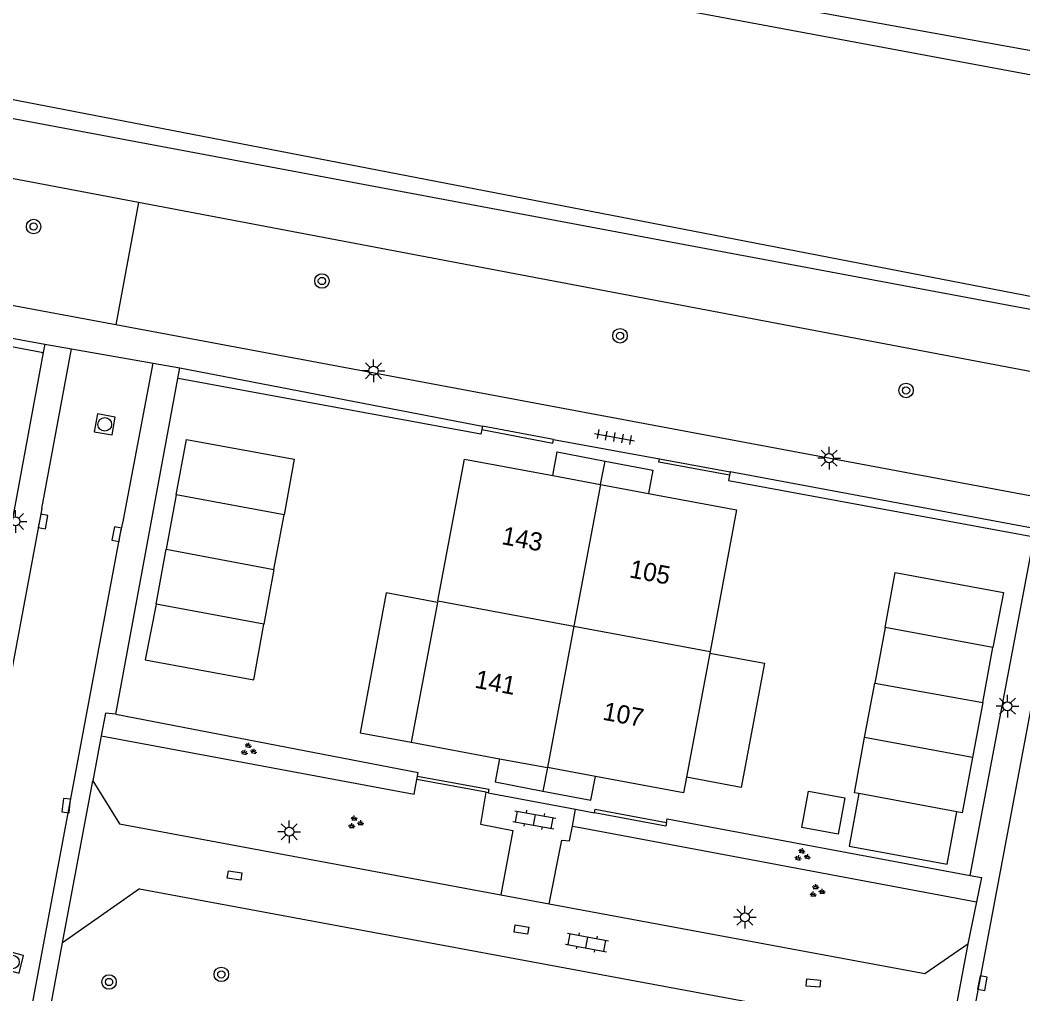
# Model space of a CAD drawing. Extents: x 124000 to 128010, y 398999 to 403000.
# Drawn here: x 126780.7 to 126835.9, y 399506.5 to 399560.1 of the extents above; entities that cross this region are included whole.
import ezdxf

# ---------------------------------------------------------------- set-up
doc = ezdxf.new("R2010")
doc.units = 0
for name, color, linetype in [('gg-afsc-hekwerk', 7, 'Continuous'), ('gg-afsc-muur', 7, 'Continuous'), ('gg-anno-huisnummerreeks BGT', 7, 'Continuous'), ('gg-bbg-bijgebouw', 7, 'Continuous'), ('gg-bbg-gedigitaliseerde bijgebouw', 7, 'Continuous'), ('gg-bbg-hoofdgebouw', 7, 'Continuous'), ('gg-bbg-luifel en loopbrug', 7, 'Continuous'), ('gg-bbg-tussenscheiding', 7, 'Continuous'), ('gg-knt-BGT kruinlijn', 7, 'Continuous'), ('gg-knt-verharding', 7, 'Continuous'), ('gg-kntw-beschoeiing', 7, 'Continuous'), ('gt-grn-groengrens', 7, 'Continuous'), ('gt-grn-vlakafsluiter', 7, 'Continuous'), ('gt-grn-weggrens', 7, 'Continuous'), ('gt-symb-boom', 7, 'Continuous'), ('gt-symb-groenvak', 7, 'Continuous'), ('gt-symb-klinker verharding', 7, 'Continuous'), ('gt-symb-kolk', 7, 'Continuous'), ('gt-symb-kolk center center', 7, 'Continuous'), ('gt-symb-lichtmast', 7, 'Continuous'), ('gt-symb-rioolschacht', 7, 'Continuous'), ('gt-symb-tegel verharding', 7, 'Continuous')]:
    doc.layers.add(name, color=color, linetype=linetype)

# ---------------------------------------------------------------- blocks, each defined once
blk = doc.blocks.new('gt0-KOLK')
at = {"layer": 'gt-symb-kolk'}
blk.add_lwpolyline([(0, 0), (0.375, 0), (0.375, 0.4), (-0.375, 0.4), (-0.375, 0), (0, 0)], dxfattribs=at)
blk = doc.blocks.new('gt0-LMAST')
at = {"layer": 'gt-symb-lichtmast'}
for p, q in [((-0.005, 0.246), (-0.005, 0.621)), ((-0.182, 0.173), (-0.447, 0.438)), ((0.172, 0.173), (0.437, 0.438)), ((-0.255, -0.004), (-0.63, -0.004)), ((-0.182, -0.181), (-0.447, -0.446)), ((-0.005, -0.254), (-0.005, -0.629)), ((0.437, -0.446), (0.172, -0.181)), ((0.245, -0.004), (0.62, -0.004))]:
    blk.add_line(p, q, dxfattribs=at)
blk.add_circle((-0.005, -0.004), 0.25, dxfattribs=at)
blk = doc.blocks.new('gt0-BOOM')
at = {"layer": 'gt-symb-boom'}
for radius in [0.4, 0.2]:
    blk.add_circle((0, 0), radius, dxfattribs=at)
blk = doc.blocks.new('gt0-GRVAK')
at = {"layer": 'gt-symb-groenvak'}
for p, q in [((-0.11, 0.189), (-0.228, 0.24)), ((-0.182, 0.153), (0.088, 0.153)), ((-0.091, 0.211), (-0.156, 0.322)), ((-0.047, 0.214), (-0.047, 0.393)), ((-0.004, 0.211), (0.061, 0.322)), ((0.015, 0.189), (0.133, 0.24)), ((0.262, -0.052), (0.197, 0.059)), ((0.305, -0.049), (0.305, 0.13)), ((0.349, -0.052), (0.414, 0.059)), ((-0.245, -0.228), (-0.363, -0.177)), ((-0.318, -0.264), (-0.047, -0.264)), ((-0.226, -0.206), (-0.291, -0.095)), ((-0.183, -0.203), (-0.183, -0.024)), ((-0.139, -0.206), (-0.074, -0.095)), ((-0.12, -0.228), (-0.002, -0.177)), ((0.243, -0.074), (0.125, -0.023)), ((0.17, -0.11), (0.441, -0.11)), ((0.368, -0.074), (0.486, -0.023))]:
    blk.add_line(p, q, dxfattribs=at)
blk = doc.blocks.new('gt0-TEG1')
at = {"layer": 'gt-symb-tegel verharding'}
for p, q in [((-1.125, 0), (1.125, 0)), ((-0.9, -0.25), (-0.9, 0.25)), ((-0.45, -0.25), (-0.45, 0.25)), ((0, -0.25), (0, 0.25)), ((0.45, -0.25), (0.45, 0.25)), ((0.9, -0.25), (0.9, 0.25))]:
    blk.add_line(p, q, dxfattribs=at)
blk = doc.blocks.new('gt0-KL1')
at = {"layer": 'gt-symb-klinker verharding'}
for p, q in [((-1.15, 0.3), (1.15, 0.3)), ((-1, -0.3), (-1, 0.3)), ((-0.5, 0.3), (-0.5, 0.45)), ((0, -0.3), (0, 0.3)), ((0.5, 0.3), (0.5, 0.45)), ((1, -0.3), (1, 0.3)), ((-1.15, -0.3), (1.15, -0.3)), ((-0.5, -0.45), (-0.5, -0.3)), ((0.5, -0.45), (0.5, -0.3))]:
    blk.add_line(p, q, dxfattribs=at)
blk = doc.blocks.new('gt0-KOLKCC')
at = {"layer": 'gt-symb-kolk center center'}
blk.add_lwpolyline([(-0.375, 0.2), (0.375, 0.2), (0.375, -0.2), (-0.375, -0.2)], close=True, dxfattribs=at)
blk = doc.blocks.new('gt0-RS')
at = {"layer": 'gt-symb-rioolschacht'}
blk.add_lwpolyline([(-0.5, -0.5), (0.5, -0.5), (0.5, 0.5), (-0.5, 0.5)], close=True, dxfattribs=at)
blk.add_circle((0, 0), 0.375, dxfattribs=at)

msp = doc.modelspace()

# ---------------------------------------------------------------- linework, layer by layer
at = {"layer": 'gg-afsc-hekwerk'}
for p, q in [((126781.846, 399541.841), (126765.496, 399544.831)), ((126806.048, 399537.335), (126789.372, 399540.394)), ((126819.677, 399534.791), (126836.523, 399531.69)), ((126785.931, 399521.922), (126802.585, 399518.705)), ((126816.307, 399516.161), (126832.985, 399513.037))]:
    msp.add_line(p, q, dxfattribs=at)
at = {"layer": 'gg-afsc-muur'}
for p, q in [((126806.13, 399537.772), (126806.095, 399537.589)), ((126810.049, 399537.042), (126806.13, 399537.772)), ((126815.875, 399535.976), (126819.765, 399535.264)), ((126819.765, 399535.264), (126819.731, 399535.078)), ((126802.515, 399518.325), (126802.55, 399518.516)), ((126806.323, 399517.621), (126802.515, 399518.325)), ((126806.439, 399517.6), (126806.323, 399517.621))]:
    msp.add_line(p, q, dxfattribs=at)
for points in [[(126806.095, 399537.589), (126810.01, 399536.838), (126810.049, 399537.042)], [(126819.731, 399535.078), (126815.84, 399535.788), (126815.875, 399535.976)], [(126802.55, 399518.516), (126806.474, 399517.791), (126806.439, 399517.6)], [(126812.307, 399516.486), (126812.344, 399516.687), (126816.269, 399515.959)], [(126816.269, 399515.959), (126816.232, 399515.758), (126812.307, 399516.486)]]:
    msp.add_lwpolyline(points, dxfattribs=at)
at = {"layer": 'gg-bbg-bijgebouw'}
for p, q in [((126789.264, 399533.997), (126788.714, 399531.004)), ((126795.202, 399532.905), (126789.264, 399533.997)), ((126794.648, 399529.896), (126795.202, 399532.905)), ((126788.157, 399527.975), (126788.714, 399531.004)), ((126794.648, 399529.896), (126794.094, 399526.883)), ((126794.094, 399526.883), (126788.157, 399527.975)), ((126828.302, 399526.696), (126827.734, 399523.638)), ((126834.244, 399525.592), (126828.302, 399526.696)), ((126833.681, 399522.562), (126834.244, 399525.592)), ((126827.179, 399520.647), (126827.734, 399523.638)), ((126833.681, 399522.562), (126833.12, 399519.544)), ((126833.12, 399519.544), (126827.179, 399520.647))]:
    msp.add_line(p, q, dxfattribs=at)
at = {"layer": 'gg-bbg-gedigitaliseerde bijgebouw'}
msp.add_lwpolyline([(126824.092, 399517.682), (126826.087, 399517.314), (126825.718, 399515.32), (126823.724, 399515.688), (126824.092, 399517.682)], dxfattribs=at)
at = {"layer": 'gg-bbg-hoofdgebouw'}
for p, q in [((126809.996, 399535.062), (126812.635, 399534.57)), ((126812.635, 399534.57), (126815.274, 399534.078)), ((126803.653, 399528.067), (126802.211, 399520.374)), ((126803.672, 399528.168), (126803.653, 399528.067)), ((126818.649, 399525.284), (126817.37, 399518.447)), ((126818.665, 399525.371), (126818.649, 399525.284)), ((126802.211, 399520.374), (126807.068, 399519.471)), ((126807.068, 399519.471), (126809.707, 399518.98)), ((126812.346, 399518.489), (126809.707, 399518.98))]:
    msp.add_line(p, q, dxfattribs=at)
for points in [[(126803.672, 399528.168), (126805.134, 399535.968), (126809.996, 399535.062)], [(126815.274, 399534.078), (126820.125, 399533.175), (126818.665, 399525.371)], [(126817.37, 399518.447), (126817.209, 399517.584), (126812.346, 399518.489)]]:
    msp.add_lwpolyline(points, dxfattribs=at)
at = {"layer": 'gg-bbg-luifel en loopbrug'}
for p, q in [((126812.635, 399534.57), (126812.881, 399535.859)), ((126809.707, 399518.98), (126809.461, 399517.691)), ((126832.247, 399516.549), (126826.859, 399517.549))]:
    msp.add_line(p, q, dxfattribs=at)
for points in [[(126789.264, 399533.997), (126789.829, 399537.045), (126795.763, 399535.953), (126795.202, 399532.905)], [(126809.996, 399535.062), (126810.245, 399536.363), (126812.881, 399535.859)], [(126812.881, 399535.859), (126815.518, 399535.354), (126815.274, 399534.078)], [(126828.302, 399526.696), (126828.865, 399529.727), (126834.818, 399528.621), (126834.244, 399525.592)], [(126803.653, 399528.067), (126800.831, 399528.595), (126799.4, 399520.897), (126802.211, 399520.374)], [(126788.157, 399527.975), (126787.551, 399524.913), (126793.53, 399523.814), (126794.094, 399526.883)], [(126818.649, 399525.284), (126821.654, 399524.722), (126820.374, 399517.886), (126817.37, 399518.447)], [(126826.859, 399517.549), (126826.613, 399517.595), (126827.179, 399520.647)], [(126807.068, 399519.471), (126806.824, 399518.196), (126809.461, 399517.691)], [(126833.12, 399519.544), (126832.542, 399516.494), (126832.247, 399516.549)], [(126809.461, 399517.691), (126812.097, 399517.187), (126812.346, 399518.489)], [(126826.859, 399517.549), (126826.326, 399514.664), (126831.714, 399513.668), (126832.247, 399516.549)]]:
    msp.add_lwpolyline(points, dxfattribs=at)
at = {"layer": 'gg-bbg-tussenscheiding'}
for p, q in [((126812.635, 399534.57), (126811.17, 399526.769)), ((126788.714, 399531.004), (126794.648, 399529.896)), ((126803.672, 399528.168), (126811.17, 399526.769)), ((126811.17, 399526.769), (126809.707, 399518.98)), ((126811.17, 399526.769), (126818.665, 399525.371)), ((126827.734, 399523.638), (126833.681, 399522.562))]:
    msp.add_line(p, q, dxfattribs=at)
at = {"layer": 'gg-knt-BGT kruinlijn'}
msp.add_line((126950.486, 399519.162), (126787.178, 399550.094), dxfattribs=at)
msp.add_lwpolyline([(126787.178, 399550.094), (126703.342, 399565.974), (126686.788, 399569.405), (126682.263, 399572.046), (126679.171, 399572.084)], dxfattribs=at)
at = {"layer": 'gg-knt-verharding'}
for p, q in [((126785.932, 399543.354), (126678.7, 399563.39)), ((126765.592, 399545.34), (126782.023, 399542.289)), ((126949.326, 399512.823), (126785.932, 399543.354)), ((126782.023, 399542.289), (126781.937, 399541.824)), ((126782.023, 399542.289), (126783.493, 399542.032)), ((126781.937, 399541.824), (126778.504, 399523.3)), ((126781.855, 399533.25), (126783.493, 399542.032)), ((126783.493, 399542.032), (126787.991, 399541.246)), ((126786.367, 399532.624), (126787.991, 399541.246)), ((126787.991, 399541.246), (126789.453, 399540.991)), ((126789.344, 399540.399), (126789.453, 399540.991)), ((126789.453, 399540.991), (126806.13, 399537.772)), ((126785.931, 399521.922), (126789.344, 399540.399)), ((126810.049, 399537.042), (126815.875, 399535.976)), ((126836.606, 399532.128), (126819.765, 399535.264)), ((126781.855, 399533.25), (126775.653, 399500)), ((126832.985, 399513.037), (126836.523, 399531.69)), ((126836.357, 399522.348), (126832.134, 399500)), ((126785.138, 399520.734), (126784.673, 399518.254)), ((126806.439, 399517.6), (126811.258, 399516.685)), ((126811.084, 399515.764), (126811.258, 399516.685)), ((126787.248, 399512.313), (126783.004, 399509.344)), ((126787.248, 399512.313), (126828.442, 399504.675)), ((126807.149, 399511.981), (126809.811, 399511.486)), ((126833.338, 399511.601), (126832.854, 399509.272)), ((126782.371, 399505.967), (126783.004, 399509.344))]:
    msp.add_line(p, q, dxfattribs=at)
for points in [[(126780.221, 399500), (126786.183, 399531.789), (126786.367, 399532.624)], [(126785.931, 399521.922), (126785.371, 399521.98), (126785.138, 399520.734)], [(126784.673, 399518.254), (126786.133, 399515.887), (126807.149, 399511.981)], [(126806.323, 399517.621), (126806.012, 399515.874), (126807.796, 399515.513), (126807.149, 399511.981)], [(126809.811, 399511.486), (126810.494, 399514.995), (126810.931, 399514.957), (126811.084, 399515.764)], [(126832.985, 399513.037), (126833.616, 399512.939), (126833.338, 399511.601)], [(126809.811, 399511.486), (126830.484, 399507.644), (126832.854, 399509.272)]]:
    msp.add_lwpolyline(points, dxfattribs=at)
at = {"layer": 'gg-kntw-beschoeiing'}
for p, q in [((126869.97, 399550.825), (126754.532, 399572.364)), ((126814.862, 399549.063), (126758.462, 399559.96)), ((126867.862, 399538.822), (126814.862, 399549.063))]:
    msp.add_line(p, q, dxfattribs=at)
at = {"layer": 'gt-grn-groengrens'}
for p, q in [((126787.178, 399550.094), (126785.932, 399543.354)), ((126811.258, 399516.685), (126812.307, 399516.486)), ((126811.084, 399515.764), (126811.503, 399515.685)), ((126811.503, 399515.685), (126833.338, 399511.601))]:
    msp.add_line(p, q, dxfattribs=at)
for points in [[(127031.407, 399516.954), (127031.756, 399518.92), (127029.879, 399522.161), (127009.635, 399525.925), (127000, 399527.778), (126870.175, 399551.993), (126857.55, 399554.628), (126778.853, 399568.809), (126692.438, 399585.276), (126688.731, 399584.708)], [(126679.888, 399575.899), (126683.061, 399575.383), (126687.279, 399572.619), (126691.934, 399571.31), (126814.728, 399548.258), (126867.774, 399538.33), (127022.231, 399507.612), (127025.36, 399507.675), (127027.276, 399508.355), (127030.476, 399511.716), (127030.741, 399513.207)], [(126785.138, 399520.734), (126802.366, 399517.512), (126802.515, 399518.325)]]:
    msp.add_lwpolyline(points, dxfattribs=at)
at = {"layer": 'gt-grn-vlakafsluiter'}
for p, q in [((126781.846, 399541.841), (126781.937, 399541.824)), ((126789.344, 399540.399), (126789.372, 399540.394)), ((126806.095, 399537.589), (126806.048, 399537.335)), ((126819.731, 399535.078), (126819.677, 399534.791)), ((126802.55, 399518.516), (126802.585, 399518.705)), ((126816.269, 399515.959), (126816.307, 399516.161))]:
    msp.add_line(p, q, dxfattribs=at)
at = {"layer": 'gt-grn-weggrens'}
for p, q in [((126783.004, 399509.344), (126784.673, 399518.254)), ((126832.854, 399509.272), (126831.228, 399500.561))]:
    msp.add_line(p, q, dxfattribs=at)

# ---------------------------------------------------------------- block references
at = {"layer": 'gt-symb-boom'}
for p in [(126781.41, 399548.765), (126797.289, 399545.769), (126813.705, 399542.752), (126829.459, 399539.746), (126791.747, 399507.599), (126785.562, 399507.18)]:
    msp.add_blockref('gt0-BOOM', p, dxfattribs=at)
at = {"layer": 'gt-symb-groenvak'}
for p, rotation in [((126793.236, 399519.954), -10.950434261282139), ((126823.73, 399514.146), -10.602058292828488)]:
    msp.add_blockref('gt0-GRVAK', p, dxfattribs=dict(at, rotation=rotation))
for p in [(126799.117, 399515.952), (126824.532, 399512.18)]:
    msp.add_blockref('gt0-GRVAK', p, dxfattribs=at)
at = {"layer": 'gt-symb-klinker verharding'}
for p, rotation in [((126808.99, 399516.105), -10.30997039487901), ((126811.883, 399509.354), -10.545734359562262)]:
    msp.add_blockref('gt0-KL1', p, dxfattribs=dict(at, rotation=rotation))
at = {"layer": 'gt-symb-kolk'}
for p, rotation in [((126781.73, 399532.564), -100.30997039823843), ((126786.183, 399531.789), 79.39794170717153), ((126783.403, 399516.863), 83.22321716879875), ((126833.467, 399507.148), -100.78161673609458)]:
    msp.add_blockref('gt0-KOLK', p, dxfattribs=dict(at, rotation=rotation))
at = {"layer": 'gt-symb-kolk center center'}
for p, rotation in [((126792.476, 399513.043), 171.72410716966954), ((126808.276, 399510.065), -8.802804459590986), ((126824.347, 399507.119), 174.83669318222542)]:
    msp.add_blockref('gt0-KOLKCC', p, dxfattribs=dict(at, rotation=rotation))
at = {"layer": 'gt-symb-lichtmast'}
for p in [(126800.133, 399540.831), (126825.222, 399536.02), (126780.415, 399532.536), (126835.046, 399522.365), (126795.491, 399515.454), (126820.592, 399510.747)]:
    msp.add_blockref('gt0-LMAST', p, dxfattribs=at)
at = {"layer": 'gt-symb-rioolschacht'}
for p, rotation in [((126785.328, 399537.877), 79.74640197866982), ((126780.244, 399508.28), 75.93596328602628)]:
    msp.add_blockref('gt0-RS', p, dxfattribs=dict(at, rotation=rotation))
at = {"layer": 'gt-symb-tegel verharding', "rotation": -10.366322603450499}
msp.add_blockref('gt0-TEG1', (126813.402, 399537.18), dxfattribs=at)

# ---------------------------------------------------------------- texts
at = {"layer": 'gg-anno-huisnummerreeks BGT'}
for s, p in [('143', (126807.141, 399531.29)), ('105', (126814.174, 399529.46)), ('141', (126805.66, 399523.389)), ('107', (126812.709, 399521.624))]:
    msp.add_text(s, height=1, rotation=349.4, dxfattribs=at).set_placement(p)

doc.saveas('drawing.dxf')
